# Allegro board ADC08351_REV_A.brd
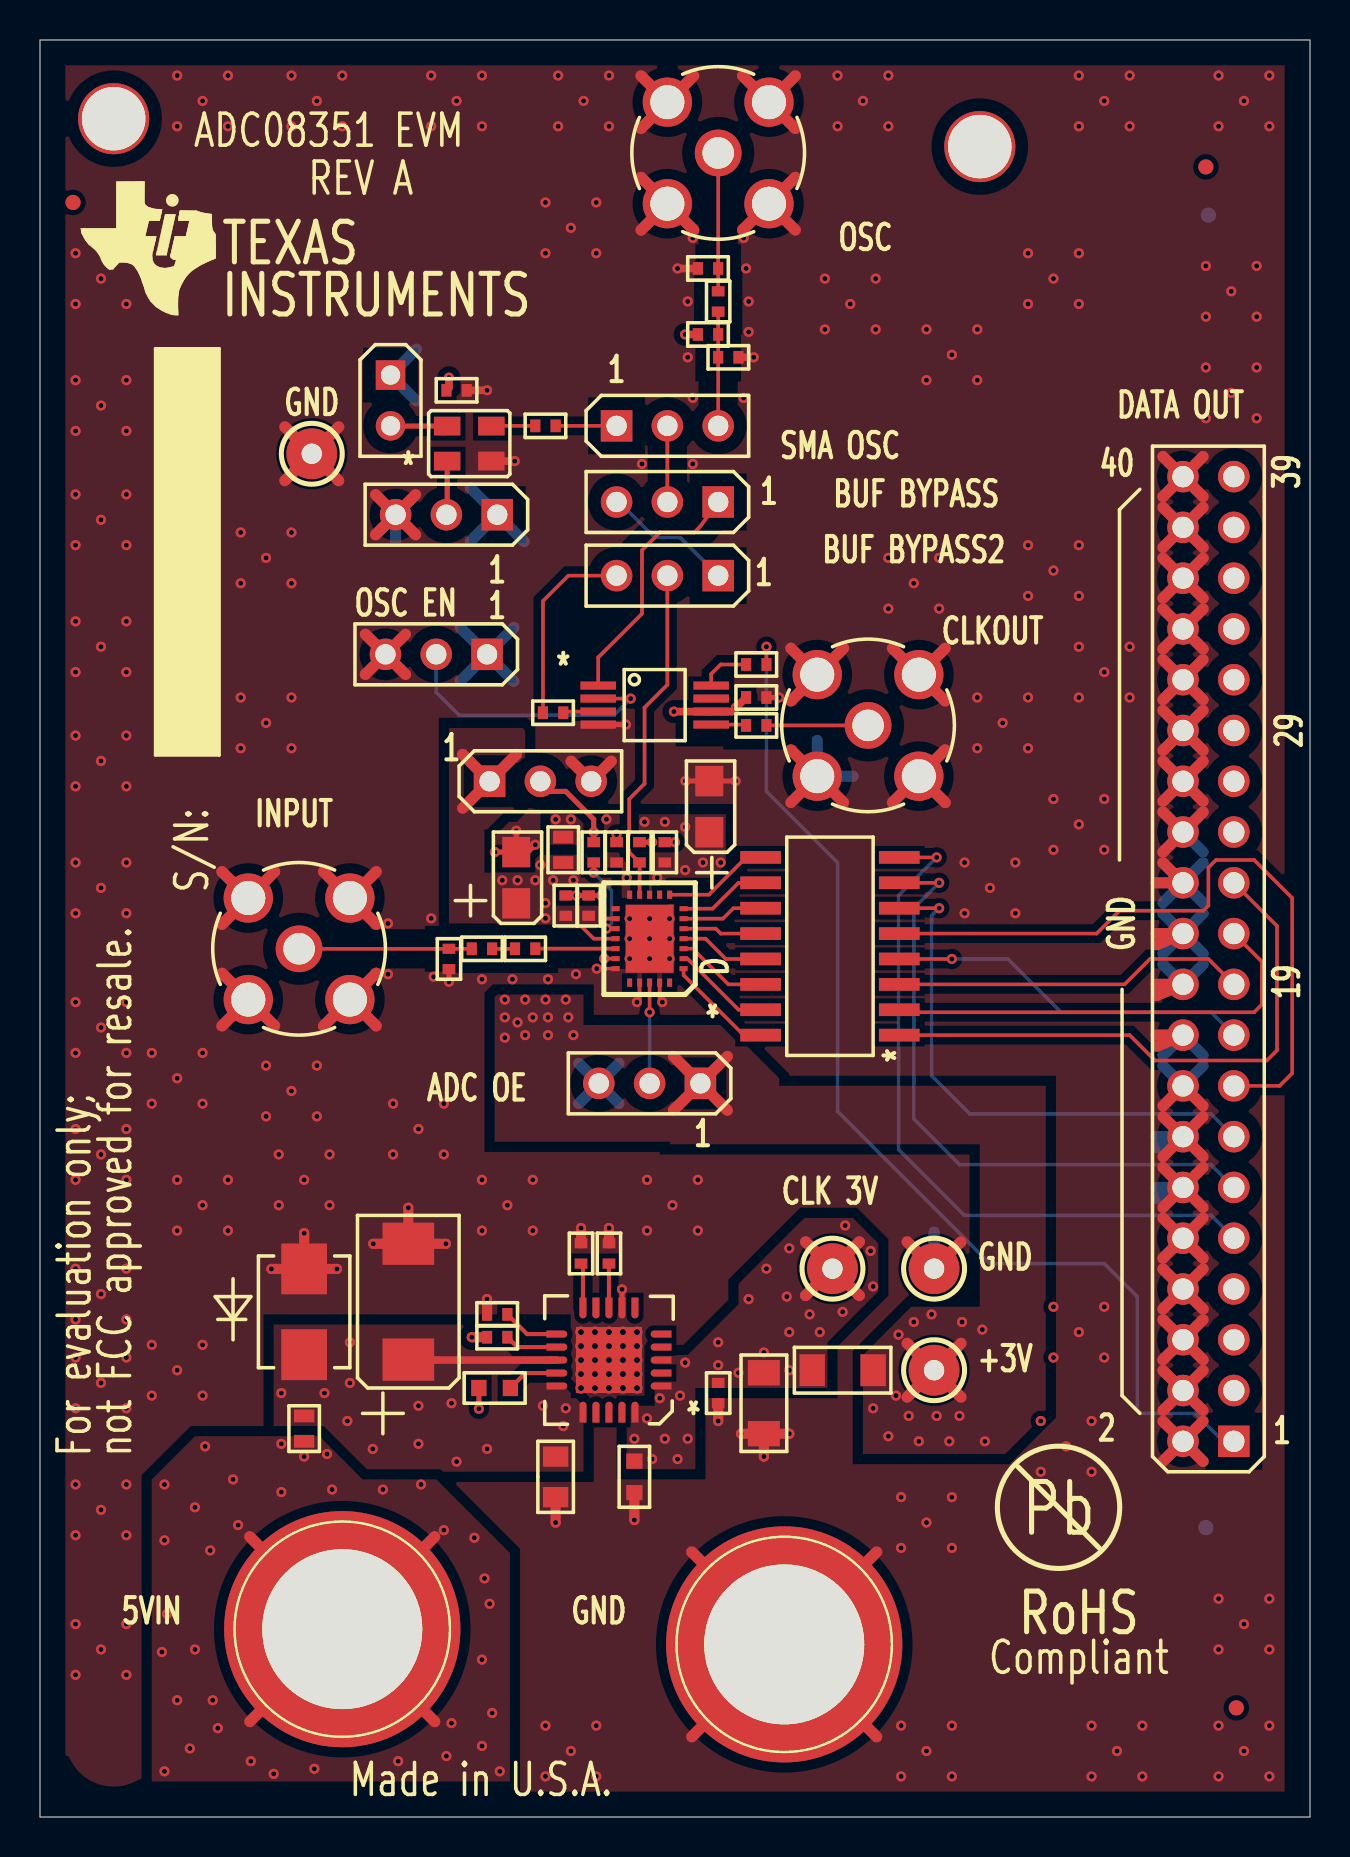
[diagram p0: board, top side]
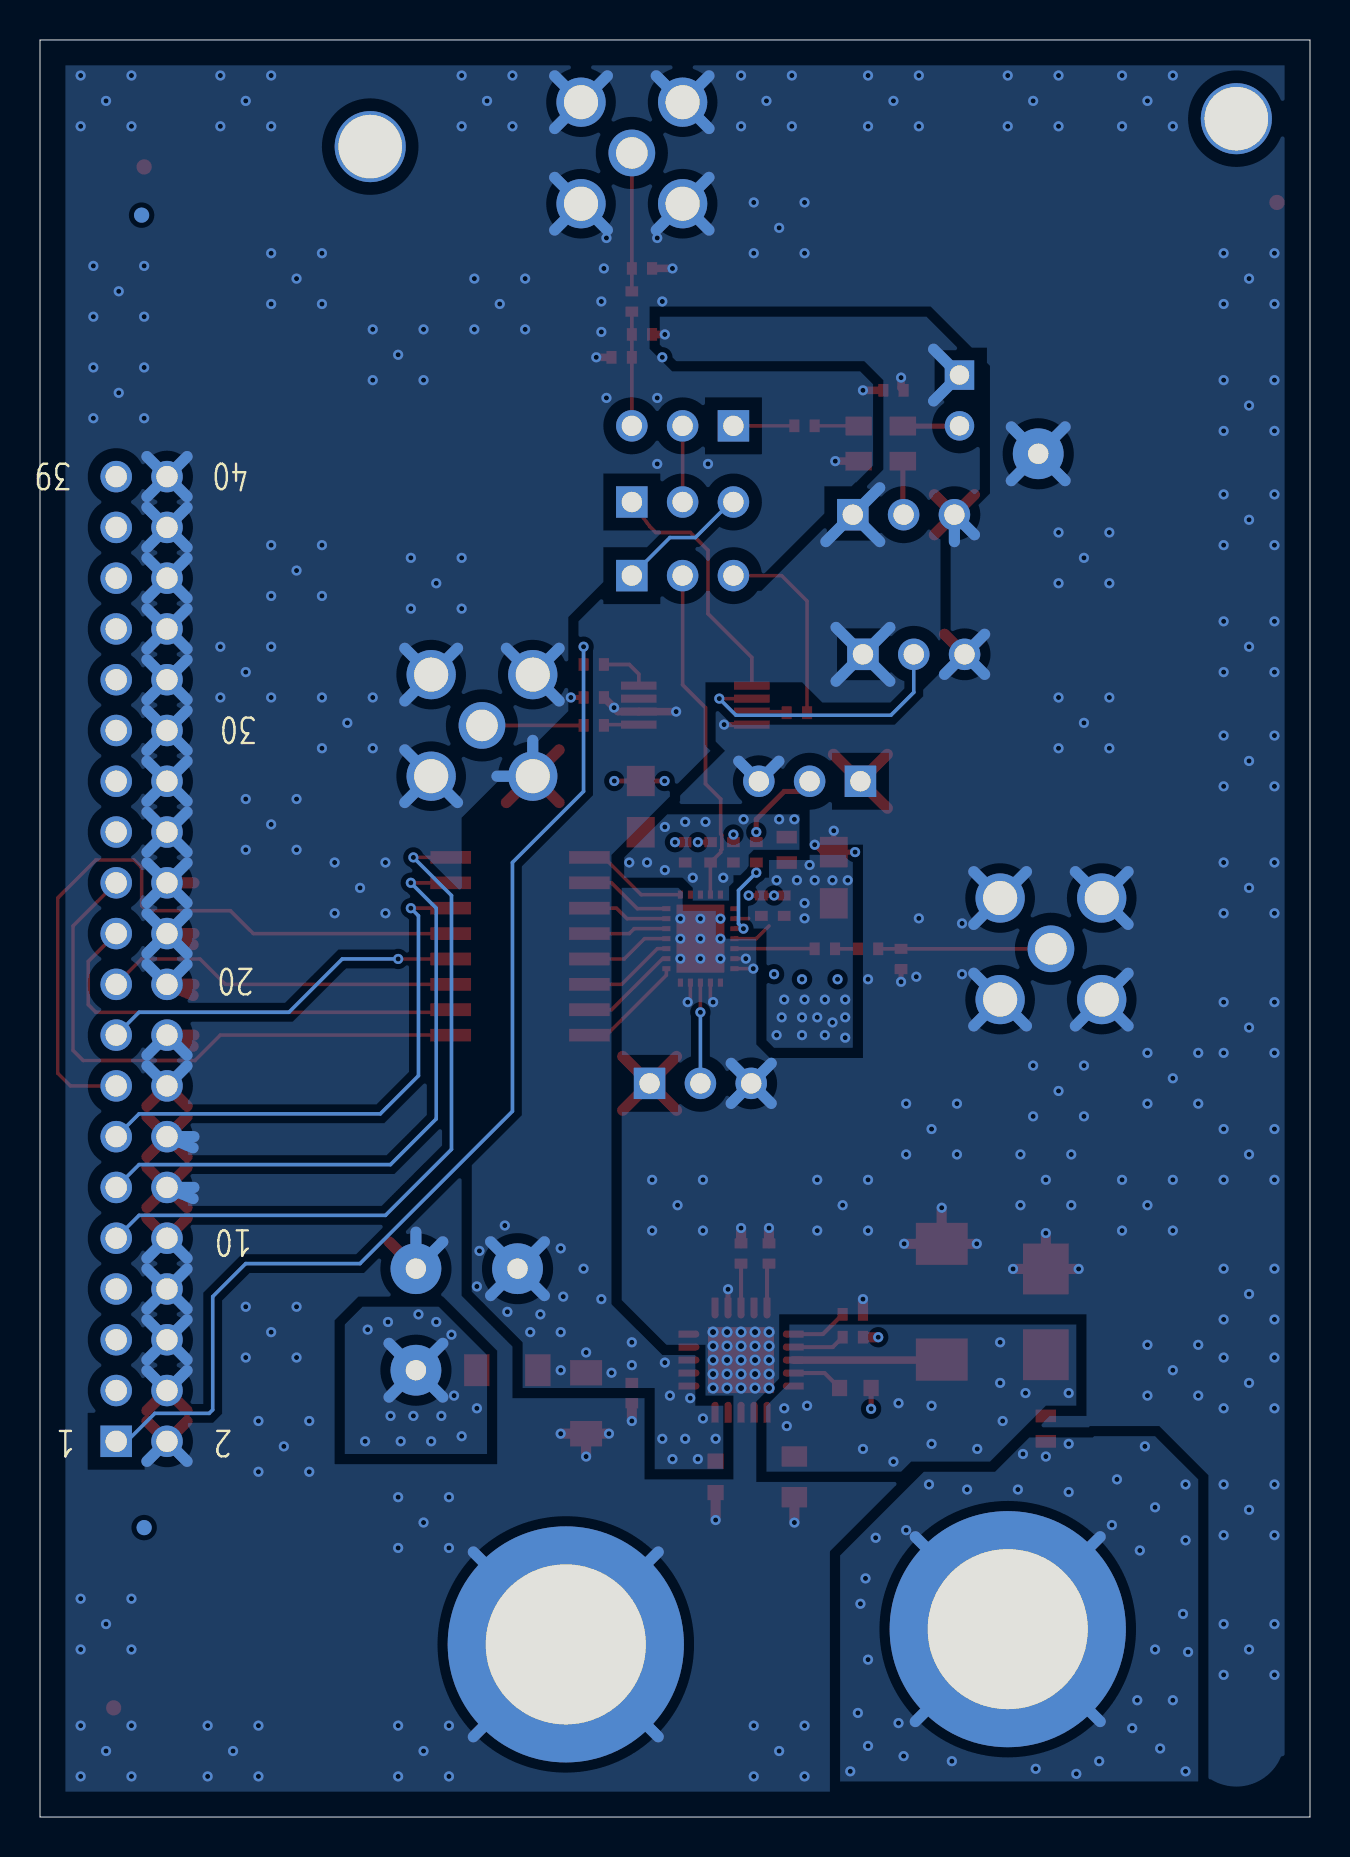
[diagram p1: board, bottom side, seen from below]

Outline 63.5 x 88.9 mm; copper layers: TOP, GND1, GND2, BOTTOM. Coordinates in mm from the lower left corner of the outline.
Outline path: 0,88.9 0,0 63.5,0 63.5,88.9 0,88.9

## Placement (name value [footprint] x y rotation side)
C1  10uF  [TANT_A]  23.81 46.99 90 top
C2  .1uF  [0402]  27.43 45.59 90 top
C3  .1uF  [0402]  26.29 45.59 90 top
C4  10uF  [TANT_A]  33.46 50.55 90 top
C5  .1uF  [0402]  28.83 48.26 90 top
C6  .1uF  [0402]  31.24 48.26 90 top
C7  2.2uF  [0402]  22.1 43.43 0 top
C8  .01uF  [0402]  20.83 71.37 0 top
C9  .1uF  [0402]  33.91 75.82 270 top
C10  100uF  [TANT_D]  18.41 25.78 90 top
C11  10uF  [0805]  25.78 17.02 270 top
C12  .1uF  [0402]  33.91 21.21 270 top
C13  1.0uF  [0603]  29.72 17.02 270 top
C14  47uF  [1206]  36.2 20.7 270 top
C20  1.0uF  [0603]  22.73 21.46 180 top
C21  .1uF  [0402]  35.81 56.01 0 top
D1  S1AB-13-F  [DIODE_S1AB_SMB]  13.21 25.27 90 top
FB1  600 OHM @ 100MHz  [IND_0603]  26.16 48.39 90 top
FB2  330 OHM @ 100MHz  [IND_0603]  13.21 19.43 90 top
FB3  120 OHM @ 100MHz  [1206]  40.13 22.35 0 top
J1  HDR, THVT, 40POS, .100  [HDR_THVT_2X20_100_M]  59.69 18.8 180 top
J2  SMA, THVT,  50OHMS  [SMA_THVT_312X312]  12.95 43.43 90 top
J3  SMA, THVT,  50OHMS  [SMA_THVT_312X312]  33.91 83.25 0 top
J4  RED  [JACK_THVT_BANANA_315DRILL]  15.11 9.4 90 top
J5  BLK  [JACK_THVT_BANANA_315DRILL]  37.21 8.64 90 top
J6  SMA, THVT,  50OHMS  [SMA_THVT_312X312]  41.4 54.61 0 top
JP1  HEADER, 3POS, .100  [HDR_THVT_1X3_100_M]  33.02 36.7 270 top
JP2  HEADER, 3POS, .100  [HDR_THVT_1X3_100_M]  28.83 69.6 90 top
JP3  HEADER, 3POS, .100  [HDR_THVT_1X3_100_M]  33.91 65.79 270 top
JP4  HEADER, 3POS, .100  [HDR_THVT_1X3_100_M]  22.35 58.17 270 top
JP5  HEADER, 3POS, .100  [HDR_THVT_1X3_100_M]  33.91 62.1 270 top
JP6  HEADER, 3POS, .100  [HDR_THVT_1X3_100_M]  22.48 51.82 90 top
JP8  HDR, 2POS, .100  [HDR_THVT_1X2_100_M]  17.53 72.14 0 top
JP9  HEADER, 3POS, .100  [HDR_THVT_1X3_100_M]  22.86 65.15 270 top
MT1  STANDOFF, FEMALE, 4-40 X  1/4"  [MFG125_PLATED]  3.68 84.96 0 top
MT4  STANDOFF, FEMALE, 4-40 X  1/4"  [MFG125_PLATED]  46.99 83.57 0 top
NOREF  -  []  258.7 174.12 0 top
NOREF#2  -  [unnamed#2]  58.29 82.55 0 top
NOREF#3  -  []  8.32 46.15 90 top
NOREF#4  -  []  51.94 8.78 0 top
NOREF#5  -  []  5.71 57.53 0 top
NOREF#6  -  []  0 0 90 top
NOREF#7  -  []  2.04 75.14 0 top
NOREF#8  -  []  0 88.9 0 top
NOREF#9  -  []  48.9 14.22 0 top
NOREF#10  -  [unnamed#2]  59.82 5.46 0 top
NOREF#11  -  []  2.44 17.93 90 top
NOREF#12  -  [unnamed#2]  1.65 80.77 0 top
NOREF#13  -  []  15.37 1.14 0 top
NOREF#14  -  []  185.29 62.97 0 top
NOREF#15  -  []  84.84 78.11 180 bottom
NOREF#16  -  [unnamed#2]  58.42 80.14 180 bottom
NOREF#17  -  [unnamed#2]  58.29 14.48 180 bottom
R2  47  [0402]  24.26 43.43 0 top
R3  51  [0402]  20.45 42.93 270 top
R4  330  [0402]  29.97 48.26 90 top
R5  10k  [0402]  27.69 48.26 90 top
R8  100  [0402]  33.4 74.17 0 top
R9  49.9  [0402]  33.4 77.47 0 top
R10  100  [0402]  34.42 73.02 0 top
R11  0  [0402]  22.86 24 0 top
R12  0  [0402]  22.86 25.15 0 top
R13  0  [0402]  27.05 28.19 270 top
R14  0  [0402]  28.45 28.19 270 top
R15  22.1  [0402]  25.65 55.24 0 top
R16  22.1  [0402]  35.81 54.61 0 top
R18  22.1  [0402]  35.81 57.66 0 top
R19  22.1  [0402]  25.27 69.6 180 top
RN1  22 OHM  [RNET_16_225X445_50]  39.5 41.66 90 top
TP1  BLK  [TP_THVT_100_RND_GND]  13.59 68.2 90 top
TP2  BLU  [TP_THVT_100_RND]  44.7 22.35 0 top
TP3  BLK  [TP_THVT_100_RND_GND]  44.7 27.43 0 top
TP4  BLU  [TP_THVT_100_RND]  39.62 27.43 0 top
U1  ADC08351  [WQFN_24_157X197_0P50MM]  30.48 43.94 180 top
U2  TPS7A4700  [QFN20_RGW_P65PITCH]  28.45 22.86 180 top
U3  CDCV304PW  [TSSOP_8_177X122_26]  30.73 55.63 0 top
Y1  40MHz  [XTAL_4_SM_102X130]  21.46 68.71 0 top

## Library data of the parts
C1 C4 = CAP_TANT_A_0
C2 C3 C5 C6 C9 C21 = CAP_0402_0.1uF
C7 = CAP_0402_2.2uF
C8 = CAP_0402_0.01uF
C10 = CAP_TANT_D_0
C11 = CAP NP_1: tolerance: 10%
C12 = CAP0603: tolerance: 10%
C13 C20 = CAP NP_0: tolerance: 10%
C14 = CAP NP_0: tolerance: 20%
D1 = DIODE_S1BB
FB1 FB2 = FERRITE_BEAD_0603_600_H
FB3 = FERRITE_BEAD_1206_120_H
J1 = HEADER_2x20_100
J2 J3 J6 = TMP_102603
J4 = BANANA_JACK_RED_RoHS
J5 = BANANA_JACK_BLK_RoHS
JP1-JP6 JP9 = JUMPER_1X3_100
JP8 = JUMPER_1X2_100
MT1 MT4 = MOUNTING_HOLE_1_3/16"
R2 = Res_0402_47
R3 = Res_0402_51_.5%: tolerance: .1%
R4 = Res_0402_330
R5 = Res_0402_10k
R8 R10 = Res_0402_100
R9 = Res_0402_49.9_H
R11-R14 = R: tolerance: 5%
R15 R16 R18 R19 = Res_0402_22.1_H
RN1 = RESNW_IS_8
TP1 TP3 = TESTPOINT_BLK
TP2 TP4 = TESTPOINT_BLUE
U1 = ADC08351
U2 = TPS7A4700
U3 = CDCV304PW
Y1 = OSC_4_SM_KYOCERA_40MHz

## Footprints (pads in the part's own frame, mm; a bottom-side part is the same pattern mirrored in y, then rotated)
0402
  rect 0.508x0.635 smd: 1(-0.508,0) 2(0.508,0)
0603
  rect 0.762x0.813 smd: 1(-0.787,0) 2(0.787,0)
0805
  rect 1.016x1.27 smd: 1(-1.016,0) 2(1.016,0)
1206
  rect 1.27x1.6 smd: 1(-1.524,0) 2(1.524,0)
DIODE_S1AB_SMB
  rect 2.54x2.286 smd: 1(2.146,0) 2(-2.146,0)
HDR_THVT_1X2_100_M
  rect 1.473x1.473 hole 0.965: 1(0,0)
  round 1.473 hole 0.965: 2(0,-2.54)
HDR_THVT_1X3_100_M
  rect 1.575x1.575 hole 1.016: 1(0,0)
  round 1.575 hole 1.016: 2(0,-2.54) 3(0,-5.08)
HDR_THVT_2X20_100_M
  rect 1.575x1.575 hole 1.067: 1(0,0)
  round 1.575 hole 1.067: 2(2.54,0) 3(0,-2.54) 4(2.54,-2.54) 5(0,-5.08) 6(2.54,-5.08) 7(0,-7.62) 8(2.54,-7.62) 9(0,-10.16) 10(2.54,-10.16) 11(0,-12.7) 12(2.54,-12.7) 13(0,-15.24) 14(2.54,-15.24) 15(0,-17.78) 16(2.54,-17.78) 17(0,-20.32) 18(2.54,-20.32) 19(0,-22.86) 20(2.54,-22.86) 21(0,-25.4) 22(2.54,-25.4) 23(0,-27.94) 24(2.54,-27.94) 25(0,-30.48) 26(2.54,-30.48) 27(0,-33.02) 28(2.54,-33.02) 29(0,-35.56) 30(2.54,-35.56) 31(0,-38.1) 32(2.54,-38.1) 33(0,-40.64) 34(2.54,-40.64) 35(0,-43.18) 36(2.54,-43.18) 37(0,-45.72) 38(2.54,-45.72) 39(0,-48.26) 40(2.54,-48.26)
IND_0603
  rect 0.635x1.016 smd: 1(-0.635,0) 2(0.635,0)
JACK_THVT_BANANA_315DRILL
  round 11.811 hole 8.001: 1(0,0)
MFG125_PLATED
  round 3.556 hole 3.175: 1(0,0)
QFN20_RGW_P65PITCH
  custom 0.09x0.09 smd: 1(-2.607,1.3) 2(-2.607,0.65) 3(-2.607,0) 4(-2.607,-0.65) 5(-2.607,-1.3) 6(-1.3,-2.607) 7(-0.65,-2.607) 8(0,-2.607) 9(0.65,-2.607) 10(1.3,-2.607) 11(2.607,-1.3) 12(2.607,-0.65) 13(2.607,0) 14(2.607,0.65) 15(2.607,1.3) 16(1.3,2.607) 17(0.65,2.607) 18(0,2.607) 19(-0.65,2.607) 20(-1.3,2.607)
  rect 3.302x3.302 smd: 21(0,0)
RNET_16_225X445_50
  rect 0.635x2.032 smd: 1(-2.54,-3.467) 2(-1.27,-3.467) 3(0,-3.467) 4(1.27,-3.467) 5(2.54,-3.467) 6(3.81,-3.467) 7(5.08,-3.467) 8(6.35,-3.467) 9(6.35,3.467) 10(5.08,3.467) 11(3.81,3.467) 12(2.54,3.467) 13(1.27,3.467) 14(0,3.467) 15(-1.27,3.467) 16(-2.54,3.467)
SMA_THVT_312X312
  round 2.337 hole 1.575: 1(0,0)
  round 2.464 hole 1.702: 2(-2.54,2.54) 3(2.54,2.54) 4(2.54,-2.54) 5(-2.54,-2.54)
TANT_A
  rect 1.524x1.397 smd: 1(-1.283,0) 2(1.283,0)
TANT_D
  rect 2.108x2.591 smd: 1(-2.896,0) 2(2.896,0)
TP_THVT_100_RND
  round 2.54 hole 1.016: 1(0,0)
TP_THVT_100_RND_GND
  round 2.54 hole 1.016: 1(0,0)
TSSOP_8_177X122_26
  rect 1.778x0.406 smd: 1(-2.825,0.975) 2(-2.825,0.325) 3(-2.825,-0.325) 4(-2.825,-0.975) 5(2.825,-0.975) 6(2.825,-0.325) 7(2.825,0.325) 8(2.825,0.975)
unnamed#2
  round 0.762 smd: (0,0)
WQFN_24_157X197_0P50MM
  rect 0.406x0.254 smd: 1(-1.7,1.5) 2(-1.7,1) 3(-1.7,0.5) 4(-1.7,0) 5(-1.7,-0.5) 6(-1.7,-1) 7(-1.7,-1.5) 13(1.7,-1.5) 14(1.7,-1) 15(1.7,-0.5) 16(1.7,0) 17(1.7,0.5) 18(1.7,1) 19(1.7,1.5)
  rect 0.254x0.406 smd: 8(-1,-2.2) 9(-0.5,-2.2) 10(0,-2.2) 11(0.5,-2.2) 12(1,-2.2) 20(1,2.2) 21(0.5,2.2) 22(0,2.2) 23(-0.5,2.2) 24(-1,2.2)
  rect 2.4x3.4 smd: 25(0,0)
XTAL_4_SM_102X130
  rect 1.321x0.94 smd: 1(-1.105,-0.876) 2(1.105,-0.876) 3(1.105,0.876) 4(-1.105,0.876)

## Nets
5V: FB2.1 J4.1
+3V: C1.1 C2.1 C3.1 FB1.1 FB3.2 JP1.1(PIN1) JP6.1(PIN1) TP2.1(TP) U1.14(VREF) U1.16(VA)
+5V: C10.1 C11.1 D1.2(CATHODE) FB2.2 U2.13(EN) U2.15(IN2) U2.16(IN1)
GND: C1.2 C2.2 C3.2 C4.2 C5.2 C6.2 C8.2 C10.2 C11.2 C12.2 C13.2 C14.2 C20.2 C21.2 D1.1(ANODE) J1.2 J1.4 J1.6 J1.8 J1.10 J1.12 J1.14 J1.16 J1.18 J1.20 J1.22 J1.24 J1.26 J1.28 J1.30 J1.32 J1.34 J1.36 J1.38 J1.40 J2.2(GND#2) J2.3(GND#3) J2.4(GND#4) J2.5(GND#5) J3.2(GND#2) J3.3(GND#3) J3.4(GND#4) J3.5(GND#5) J5.1 J6.2(GND#2) J6.3(GND#3) J6.4(GND#4) J6.5(GND#5) JP1.3(PIN3) JP4.3(PIN3) JP6.3(PIN3) JP9.3(PIN3) R3.2 R4.2 R9.1 R10.2 R11.1 R12.1 R13.1 R14.1 TP1.1(TP) TP3.1(TP) U1.18(AGND1) U1.19(AGND2) U1.21(DGND1) U1.23(DGND2) U1.25(PWRPAD) U2.7(GND) U2.21(PWRPAD) U3.4(GND) Y1.2(GND)
VIN: R2.2 U1.17(VIN)
ADC_CLK: JP2.2(PIN2) JP3.2(PIN2)
CLK: JP5.2(PIN2) R4.1 U1.11(CLK)
CLK_3V: C8.1 C12.1 C13.1 C14.1 C21.1 FB3.1 JP4.1(PIN1) JP8.1 JP9.1(PIN1) R8.1 TP4.1(TP) U2.1(OUT1) U2.3(SENSE) U2.20(OUT2) U3.6(VDD3.3V)
CLK_OUT: J6.1(CENTER) R16.2
CLKIN: JP3.1(PIN1) U3.1(CLKIN)
CLKOUT: R16.1 U3.5(X1Y1)
D0: RN1.16 U1.1(D0)
D1: RN1.15 U1.2(D1)
D2: RN1.14 U1.3(D2)
D3: RN1.13 U1.4(D3)
D4: RN1.12 U1.5(D4)
D5: RN1.11 U1.6(D5)
D6: RN1.10 U1.7(D6)
D7: RN1.9 U1.8(D7)
IN: C7.2 R2.1
INPUT: C7.1 J2.1(CENTER) R3.1
OE: JP4.2(PIN2) U3.2(OE)
OEN: JP1.2(PIN2) U1.22(\\O\E\)
OSC: C9.1 J3.1(CENTER) R9.2
OSC1: C9.2 JP2.3(PIN3) R8.2 R10.1
N19763021: C4.1 C5.1 C6.1 FB1.2 U1.10(VD#10) U1.12(VD#12)
N19764908: R5.1 U1.15(PD)
N19769118: R19.2 Y1.3(OUT)
N19769226: JP2.1(PIN1) R19.1
N19785120: C20.1 U2.14(NR)
N19785142: R14.2 U2.8(1P6V)
N19785144: R12.2 U2.11(0P2V)
N19785146: R11.2 U2.12(0P1V)
N19785156: R13.2 U2.10(0P4V)
N19799665: R15.2 U3.3(X1Y0)
N19799687: R18.1 U3.8(X1Y3)
N19799717: J1.1 R18.2
N19818955: J1.23 RN1.1
N19818957: J1.21 RN1.2
N19818959: J1.19 RN1.3
N19818961: J1.17 RN1.4
N19819026: J1.9 RN1.8
N19819028: J1.11 RN1.7
N19819030: J1.13 RN1.6
N19819032: J1.15 RN1.5
N19819185: JP3.3(PIN3) JP5.1(PIN1)
N19819218: JP5.3(PIN3) R15.1
N19819979: JP6.2(PIN2) R5.2
N19821064: JP9.2(PIN2) Y1.1(INH)
N19821339: JP8.2 Y1.4(VDD)

Pads without a net: J1 3 5 7 25 27 29 31 33 35 37 39; MT1 1; MT4 1; U1 9 13 20 24; U2 2 4 5 6 9 17 18 19; U3 7

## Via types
v1: diameter 0.508, hole 0.254, TOP to BOTTOM, 447 vias
v2: diameter 0.559, hole 0.305, TOP to BOTTOM, 25 vias

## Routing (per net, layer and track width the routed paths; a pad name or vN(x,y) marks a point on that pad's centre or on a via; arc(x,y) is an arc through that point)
5V: length 52.3
  TOP w0.559: J4.1 19.74,4.78 ; J4.1 19.74,14.02 ; J4.1 10.49,14.02 ; J4.1 10.49,4.78
  BOTTOM w0.559: J4.1 19.74,14.02 ; J4.1 10.49,4.78 ; J4.1 10.49,14.02 ; J4.1 19.74,4.78
  vias: v1(6.1,8.25) v1(6.22,16.64) v1(6.22,13.84) v1(6.22,2.29) v1(6.35,10.16) v1(6.86,5.84) v1(7.49,3.43) v1(7.75,15.49) v1(7.75,8.38) v1(8.25,18.54) v1(8.51,13.33) v1(8.64,5.84) v1(8.89,4.45) v1(9.65,16.89) v1(9.91,14.6) v1(10.54,2.79) v1(11.68,2.16) v1(12.06,18.67) v1(12.06,16.26) v1(13.21,18.03) v1(13.72,2.41) v1(14.35,18.16) v1(14.61,16.38) v1(17.14,16.38) v1(17.91,2.79) v1(19.05,16.64) v1(20.19,14.35) v1(20.32,3.05) v1(20.57,4.7) v1(21.72,13.97) v1(22.1,7.87) v1(22.1,3.56) v1(22.23,11.94) v1(22.48,10.67) v1(22.61,5.21) v1(22.99,2.29)
+3V: length 31.3
  TOP w0.178: 27.05,44.58 27.69,43.94 U1.16 ; U1.14 28.08,44.94 28.07,44.96
  TOP w0.559: JP1.1 34.37,38.05 ; JP1.1 31.67,38.05 ; JP1.1 31.67,35.36 ; JP1.1 34.37,35.36 ; TP2.1 46.05,23.7 ; TP2.1 43.36,21.01 ; TP2.1 46.05,21.01 ; TP2.1 43.36,23.7 ; 21.13,53.16 JP6.1 ; JP6.1 23.83,53.16 ; JP6.1 21.13,50.47
  BOTTOM w0.559: 43.36,23.7 TP2.1 ; TP2.1 43.36,21.01 ; TP2.1 46.05,23.7 ; TP2.1 46.05,21.01
  vias: v1(23.11,46.86) v1(23.24,40.89) v1(23.24,40) v1(23.24,38.99) v1(23.88,46.86) v1(23.88,39.75) v1(24.26,40.89) v1(24.26,39.12) v1(24.64,40) v1(24.77,46.86) v1(25.02,47.62) v1(25.27,45.72) v1(25.27,44.96) v1(25.27,40.89) v1(25.4,40) v1(25.4,39.12) v1(25.65,46.86) v1(26.29,40.89) v1(26.42,40) v1(26.67,46.86) v1(26.67,39.12) v1(41.66,20.45) v1(42.42,19.05) v1(42.8,21.08) v1(42.93,24.13) v1(43.43,20.07) v1(43.69,24.77) v1(43.94,18.8) v1(44.58,25.15) v1(44.83,20.07) v1(45.47,18.8) v1(45.97,20.07) v1(46.1,24.77) v1(47.12,24.38) v1(47.24,18.8)
+5V: length 6.2
  TOP w0.381: U2.13 19.68,22.86
  vias: v1(12.06,21.21) v1(14.22,21.21) v1(15.37,19.81) v1(15.49,23.75) v1(15.49,21.72) v1(16.64,18.41) v1(18.92,20.57) v1(18.92,18.67) v1(20.57,20.7) v1(20.83,17.78) v1(22.35,18.41) v1(25.15,20.57) v1(26.16,19.56) v1(26.29,20.45)
GND: length 956.2
  TOP w0.178: U1.23 30.98,40.9 v1(31.11,40.77) ; U1.18 v1(28.21,42.94) ; v1(29.84,40.77) 29.98,40.9 U1.21 ; U1.19 v1(27.84,42.44)
  TOP w0.254: U2.7 v1(29.1,26.4) ; v1(34.79,51.83) C4.2 v1(32.27,51.83) ; C20.2 v1(21.95,20.42) ; C6.2 v1(31.75,48.77) ; R4.2 v1(30.61,48.77) ; v1(28.07,46.1) C2.2 v1(26.8,46.1) C3.2 ; v1(24.77,48.64) 24.4,48.27 C1.2 ; C1.2 v1(22.75,48.27) ; C1.2 v1(23.81,49.34) ; C5.2 v1(28.83,49.15) ; U3.4 v1(29.3,54.65) ; C21.2 v1(36.96,56.01) ; R3.2 v1(20.45,41.78)
  TOP w0.381: R9.1 v1(31.88,77.47) ; C8.2 v1(22.35,71.37) ; R10.2 v1(35.69,73.02) ; Y1.2 v1(23.74,67.83)
  TOP w0.508: D1.1 v1(13.21,29.21) ; D1.1 v1(14.85,27.42) ; D1.1 v1(11.57,27.42) ; C10.2 v1(16.66,28.68) ; C10.2 v1(18.41,30.48) ; C10.2 v1(20.29,28.68) ; R14.1 v1(28.45,29.46) ; R13.1 v1(27.05,29.46) ; C11.2 v1(25.78,14.73) ; C14.2 v1(35.05,19.18) ; C14.2 v1(37.46,19.18) ; C14.2 v1(36.2,18.03) ; C12.2 v1(33.91,19.81) ; R12.1 v1(22.35,25.91) ; C13.2 v1(29.72,14.86) ; R11.1 v1(21.59,24)
  TOP w0.559: 56.15,68.06 J1.40 ; J1.40 58.15,68.06 ; J1.40 58.15,66.05 ; J1.40 56.15,66.05 ; J1.10 58.15,27.95 ; J1.10 58.15,29.96 ; J1.10 56.15,27.95 ; J1.10 56.15,29.96 ; J2.4 16.81,44.66 ; J2.4 14.18,47.29 ; J2.4 16.81,47.29 ; 28.56,52.82 JP6.3 26.56,52.82 ; J3.2 32.69,87.11 ; J3.2 30.05,84.47 ; J3.2 30.05,87.11 ; 56.15,32.5 57.15,31.5 ; 57.15,31.5 58.15,30.49 ; 57.15,31.5 56.15,30.49 ; 57.15,31.5 58.15,32.5 ; 37.54,50.75 J6.5 ; J6.5 40.18,50.75 ; J6.5 37.54,53.39 ; 37.54,58.47 J6.2 ; J6.2 40.18,58.47 ; J6.2 37.54,55.83 ; JP9.3 18.78,66.15 ; JP9.3 16.78,64.15 ; JP9.3 18.78,64.15 ; JP9.3 16.78,66.15 ; J2.3 11.73,47.29 ; J2.3 9.1,44.66 ; J2.3 9.1,47.29 ; J3.5 32.69,79.39 ; J3.5 30.05,82.03 ; J3.5 30.05,79.39 ; J1.34 58.15,60.44 ; J1.34 56.15,58.43 ; J1.34 56.15,60.44 ; J1.34 58.15,58.43 ; 56.15,50.81 J1.28 ; J1.28 58.15,50.81 ; J1.28 56.15,52.82 ; J1.28 58.15,52.82 ; 56.15,57.9 J1.32 ; J1.32 56.15,55.89 ; J1.32 58.15,57.9 ; J1.32 58.15,55.89 ; 14.18,39.58 J2.5 ; J2.5 16.81,39.58 ; J2.5 16.81,42.21 ; J3.3 37.77,84.47 ; J3.3 37.77,87.11 ; J3.3 35.13,87.11 ; J1.6 58.15,22.87 ; J1.6 56.15,22.87 ; J1.6 56.15,24.88 ; J1.6 58.15,24.88 ; 56.15,53.35 J1.30 ; J1.30 58.15,53.35 ; J1.30 56.15,55.36 ; J1.30 58.15,55.36 ; 16.27,57.16 JP4.3 ; JP4.3 16.27,59.17 ; JP4.3 18.28,59.17 ; JP4.3 18.28,57.16 ; 35.13,79.39 J3.4 ; J3.4 37.77,79.39 ; J3.4 37.77,82.03 ; J1.38 58.15,63.51 ; J1.38 56.15,65.52 ; J1.38 56.15,63.51 ; J1.38 58.15,65.52 ; 58.15,35.57 J1.16 56.15,35.57 ; 56.15,47.74 J1.24 55.8,46.74 ; J6.4 45.26,50.75 ; J6.4 45.26,53.39 ; J6.4 42.62,50.75 ; 56.15,20.33 J1.4 ; J1.4 58.15,20.33 ; J1.4 58.15,22.34 ; J1.4 56.15,22.34 ; 56.15,35.04 J1.14 ; J1.14 56.15,33.03 ; J1.14 58.15,35.04 ; J1.14 58.15,33.03 ; 46.05,28.78 TP3.1 43.36,28.78 ; J1.8 58.15,27.42 ; J1.8 58.15,25.41 ; J1.8 56.15,27.42 ; J1.8 56.15,25.41 ; 32.59,13.26 J5.1 ; J5.1 41.83,4.01 ; J5.1 41.83,13.26 ; J5.1 32.59,4.01 ; 56.15,17.79 J1.2 ; J1.2 56.15,19.8 ; J1.2 58.15,19.8 ; J1.2 58.15,17.79 ; J6.3 45.26,58.47 ; J6.3 42.62,58.47 ; J6.3 45.26,55.83 ; 56.15,60.97 J1.36 ; J1.36 58.15,60.97 ; J1.36 56.15,62.98 ; J1.36 58.15,62.98 ; 55.85,43.64 J1.22 55.8,44.2 ; 55.85,41.1 J1.20 55.8,41.66 ; J1.26 58.15,50.28 ; J1.26 56.15,50.28 ; J1.26 56.15,48.27 ; 55.85,38.56 J1.18 55.8,39.12 ; TP1.1 14.93,69.54 ; TP1.1 14.93,66.85 ; TP1.1 12.24,66.85 ; TP1.1 12.24,69.54 ; 9.1,39.58 J2.2 ; J2.2 9.1,42.21 ; J2.2 11.73,39.58
  GND1 w0.559: 56.15,24.88 J1.6 ; J1.6 58.15,24.88 ; J1.6 58.15,22.87 ; J1.6 56.15,22.87 ; J1.30 58.15,53.35 ; J1.30 58.15,55.36 ; J1.30 56.15,55.36 ; J1.30 56.15,53.35 ; 30.05,87.11 J3.2 ; J3.2 32.69,87.11 ; J3.2 30.05,84.47 ; J1.34 58.15,60.44 ; J1.34 58.15,58.43 ; J1.34 56.15,58.43 ; J1.34 56.15,60.44 ; 56.15,47.74 J1.24 ; J1.24 58.15,45.73 ; J1.24 58.15,47.74 ; J1.24 56.15,45.73 ; JP9.3 18.78,64.15 ; JP9.3 18.78,66.15 ; JP9.3 16.78,64.15 ; JP9.3 16.78,66.15 ; J2.5 16.81,42.21 ; J2.5 16.81,39.58 ; J2.5 14.18,39.58 ; J1.16 58.15,35.57 ; J1.16 56.15,37.58 ; J1.16 56.15,35.57 ; J1.16 58.15,37.58 ; J6.3 45.26,55.83 ; J6.3 45.26,58.47 ; J6.3 42.62,58.47 ; 57.15,31.5 58.15,30.49 ; 57.15,31.5 56.15,30.49 ; 57.15,31.5 58.15,32.5 ; 57.15,31.5 56.15,32.5 ; TP3.1 46.05,28.78 ; TP3.1 46.05,26.09 ; TP3.1 43.36,26.09 ; TP3.1 43.36,28.78 ; 56.15,25.41 J1.8 ; J1.8 58.15,27.42 ; J1.8 56.15,27.42 ; J1.8 58.15,25.41 ; J1.26 58.15,48.27 ; J1.26 58.15,50.28 ; J1.26 56.15,48.27 ; J1.26 56.15,50.28 ; J1.40 58.15,68.06 ; J1.40 56.15,68.06 ; J1.40 56.15,66.05 ; J1.40 58.15,66.05 ; 56.15,19.8 J1.2 ; J1.2 58.15,19.8 ; J1.2 56.15,17.79 ; J1.2 58.15,17.79 ; 37.54,50.75 J6.5 ; J6.5 37.54,53.39 ; J6.5 40.18,50.75 ; 56.15,27.95 J1.10 ; J1.10 56.15,29.96 ; J1.10 58.15,29.96 ; J1.10 58.15,27.95 ; J3.5 32.69,79.39 ; J3.5 30.05,79.39 ; J3.5 30.05,82.03 ; 56.15,40.65 J1.20 ; J1.20 58.15,42.66 ; J1.20 58.15,40.65 ; J1.20 56.15,42.66 ; JP4.3 18.28,57.16 ; JP4.3 16.27,59.17 ; JP4.3 18.28,59.17 ; JP4.3 16.27,57.16 ; 56.15,65.52 J1.38 ; J1.38 58.15,63.51 ; J1.38 58.15,65.52 ; J1.38 56.15,63.51 ; TP1.1 14.93,69.54 ; TP1.1 14.93,66.85 ; TP1.1 12.24,69.54 ; TP1.1 12.24,66.85 ; J1.36 58.15,60.97 ; J1.36 58.15,62.98 ; J1.36 56.15,62.98 ; J1.36 56.15,60.97 ; 56.15,35.04 J1.14 ; J1.14 56.15,33.03 ; J1.14 58.15,33.03 ; J1.14 58.15,35.04 ; 37.54,58.47 J6.2 ; J6.2 40.18,58.47 ; J6.2 37.54,55.83 ; 9.1,42.21 J2.2 ; J2.2 9.1,39.58 ; J2.2 11.73,39.58 ; 14.18,47.29 J2.4 ; J2.4 16.81,44.66 ; J2.4 16.81,47.29 ; J3.3 37.77,84.47 ; J3.3 35.13,87.11 ; J3.3 37.77,87.11 ; J6.4 45.26,53.39 ; J6.4 45.26,50.75 ; J6.4 42.62,50.75 ; 56.15,45.2 J1.22 ; J1.22 58.15,45.2 ; J1.22 58.15,43.19 ; J1.22 56.15,43.19 ; 35.13,79.39 J3.4 ; J3.4 37.77,82.03 ; J3.4 37.77,79.39 ; 26.94,35.7 JP1.3 ; JP1.3 28.94,37.71 ; JP1.3 28.94,35.7 ; JP1.3 26.94,37.71 ; 32.59,4.01 J5.1 ; J5.1 41.83,4.01 ; J5.1 41.83,13.26 ; J5.1 32.59,13.26 ; J1.32 58.15,55.89 ; J1.32 56.15,57.9 ; J1.32 56.15,55.89 ; J1.32 58.15,57.9 ; J1.18 58.15,38.11 ; J1.18 56.15,40.12 ; J1.18 58.15,40.12 ; J1.18 56.15,38.11 ; JP6.3 28.56,50.81 ; JP6.3 26.56,50.81 ; JP6.3 28.56,52.82 ; JP6.3 26.56,52.82 ; 56.15,52.82 J1.28 ; J1.28 58.15,52.82 ; J1.28 56.15,50.81 ; J1.28 58.15,50.81 ; J1.4 58.15,20.33 ; J1.4 58.15,22.34 ; J1.4 56.15,22.34 ; J1.4 56.15,20.33 ; J2.3 11.73,47.29 ; J2.3 9.1,47.29 ; J2.3 9.1,44.66
  GND2 w0.559: J1.24 58.15,45.73 ; J1.24 56.15,45.73 ; J1.24 56.15,47.74 ; J1.24 58.15,47.74 ; 14.18,47.29 J2.4 ; J2.4 16.81,47.29 ; J2.4 16.81,44.66 ; TP3.1 46.05,28.78 ; TP3.1 43.36,26.09 ; TP3.1 46.05,26.09 ; TP3.1 43.36,28.78 ; JP4.3 18.28,59.17 ; JP4.3 18.28,57.16 ; JP4.3 16.27,57.16 ; JP4.3 16.27,59.17 ; J1.34 58.15,58.43 ; J1.34 56.15,60.44 ; J1.34 58.15,60.44 ; J1.34 56.15,58.43 ; J6.5 40.18,50.75 ; J6.5 37.54,50.75 ; J6.5 37.54,53.39 ; J1.20 58.15,42.66 ; J1.20 58.15,40.65 ; J1.20 56.15,40.65 ; J1.20 56.15,42.66 ; 57.15,31.5 58.15,30.49 ; 57.15,31.5 58.15,32.5 ; 57.15,31.5 56.15,30.49 ; 57.15,31.5 56.15,32.5 ; 26.56,52.82 JP6.3 ; JP6.3 28.56,52.82 ; JP6.3 26.56,50.81 ; JP6.3 28.56,50.81 ; J3.3 37.77,84.47 ; J3.3 35.13,87.11 ; J3.3 37.77,87.11 ; 56.15,60.97 J1.36 ; J1.36 58.15,60.97 ; J1.36 58.15,62.98 ; J1.36 56.15,62.98 ; J5.1 41.83,4.01 ; J5.1 32.59,13.26 ; J5.1 32.59,4.01 ; J5.1 41.83,13.26 ; J1.18 58.15,40.12 ; J1.18 56.15,38.11 ; J1.18 58.15,38.11 ; J1.18 56.15,40.12 ; J1.22 58.15,43.19 ; J1.22 58.15,45.2 ; J1.22 56.15,45.2 ; J1.22 56.15,43.19 ; J1.16 58.15,35.57 ; J1.16 58.15,37.58 ; J1.16 56.15,37.58 ; J1.16 56.15,35.57 ; 37.54,55.83 J6.2 ; J6.2 40.18,58.47 ; J6.2 37.54,58.47 ; J1.6 58.15,22.87 ; J1.6 56.15,22.87 ; J1.6 56.15,24.88 ; J1.6 58.15,24.88 ; 35.13,79.39 J3.4 ; J3.4 37.77,82.03 ; J3.4 37.77,79.39 ; JP1.3 28.94,37.71 ; JP1.3 26.94,35.7 ; JP1.3 28.94,35.7 ; JP1.3 26.94,37.71 ; 30.05,79.39 J3.5 ; J3.5 30.05,82.03 ; J3.5 32.69,79.39 ; J6.3 45.26,58.47 ; J6.3 45.26,55.83 ; J6.3 42.62,58.47 ; 16.78,64.15 JP9.3 ; JP9.3 16.78,66.15 ; JP9.3 18.78,66.15 ; JP9.3 18.78,64.15 ; J1.2 58.15,17.79 ; J1.2 58.15,19.8 ; J1.2 56.15,19.8 ; J1.2 56.15,17.79 ; 9.1,39.58 J2.2 ; J2.2 11.73,39.58 ; J2.2 9.1,42.21 ; 56.15,25.41 J1.8 ; J1.8 56.15,27.42 ; J1.8 58.15,27.42 ; J1.8 58.15,25.41 ; 56.15,66.05 J1.40 ; J1.40 58.15,68.06 ; J1.40 58.15,66.05 ; J1.40 56.15,68.06 ; J1.10 58.15,29.96 ; J1.10 56.15,29.96 ; J1.10 58.15,27.95 ; J1.10 56.15,27.95 ; J1.38 58.15,63.51 ; J1.38 56.15,63.51 ; J1.38 58.15,65.52 ; J1.38 56.15,65.52 ; 12.24,69.54 TP1.1 ; TP1.1 14.93,69.54 ; TP1.1 12.24,66.85 ; TP1.1 14.93,66.85 ; J1.26 58.15,48.27 ; J1.26 56.15,50.28 ; J1.26 56.15,48.27 ; J1.26 58.15,50.28 ; J6.4 45.26,50.75 ; J6.4 42.62,50.75 ; J6.4 45.26,53.39 ; J2.5 16.81,42.21 ; J2.5 16.81,39.58 ; J2.5 14.18,39.58 ; J1.28 58.15,52.82 ; J1.28 56.15,50.81 ; J1.28 58.15,50.81 ; J1.28 56.15,52.82 ; 56.15,22.34 J1.4 ; J1.4 58.15,20.33 ; J1.4 58.15,22.34 ; J1.4 56.15,20.33 ; J3.2 32.69,87.11 ; J3.2 30.05,87.11 ; J3.2 30.05,84.47 ; J1.30 58.15,53.35 ; J1.30 56.15,53.35 ; J1.30 56.15,55.36 ; J1.30 58.15,55.36 ; J2.3 11.73,47.29 ; J2.3 9.1,47.29 ; J2.3 9.1,44.66 ; 56.15,35.04 J1.14 ; J1.14 58.15,33.03 ; J1.14 56.15,33.03 ; J1.14 58.15,35.04 ; 56.15,57.9 J1.32 ; J1.32 58.15,57.9 ; J1.32 56.15,55.89 ; J1.32 58.15,55.89
  BOTTOM w0.559: J1.26 58.15,50.28 ; J1.26 58.15,48.27 ; J1.26 56.15,48.27 ; J1.26 56.15,50.28 ; 56.15,60.97 J1.36 ; J1.36 58.15,62.98 ; J1.36 58.15,60.97 ; J1.36 56.15,62.98 ; J5.1 41.83,4.01 ; J5.1 32.59,4.01 ; J5.1 32.59,13.26 ; J5.1 41.83,13.26 ; 12.24,66.85 TP1.1 ; TP1.1 12.24,69.54 ; TP1.1 14.93,69.54 ; TP1.1 14.93,66.85 ; 16.78,64.15 JP9.3 17.78,63.8 ; 9.1,42.21 J2.2 ; J2.2 9.1,39.58 ; J2.2 11.73,39.58 ; 58.15,17.79 J1.2 56.15,17.79 ; J3.3 37.77,84.47 ; J3.3 35.13,87.11 ; J3.3 37.77,87.11 ; J6.4 45.26,50.75 ; J6.4 42.62,50.75 ; J6.4 45.26,53.39 ; JP1.3 28.94,37.71 ; JP1.3 26.94,35.7 ; JP1.3 28.94,35.7 ; JP1.3 26.94,37.71 ; J2.5 16.81,39.58 ; J2.5 14.18,39.58 ; J2.5 16.81,42.21 ; J6.3 45.26,58.47 ; J6.3 45.26,55.83 ; J6.3 42.62,58.47 ; 56.15,25.41 J1.8 ; J1.8 58.15,27.42 ; J1.8 56.15,27.42 ; J1.8 58.15,25.41 ; J2.3 11.73,47.29 ; J2.3 9.1,47.29 ; J2.3 9.1,44.66 ; 56.15,24.88 J1.6 ; J1.6 58.15,22.87 ; J1.6 58.15,24.88 ; J1.6 56.15,22.87 ; 26.56,52.82 JP6.3 28.56,52.82 ; 14.18,47.29 J2.4 ; J2.4 16.81,47.29 ; J2.4 16.81,44.66 ; 56.15,52.82 J1.28 ; J1.28 58.15,52.82 ; J1.28 56.15,50.81 ; J1.28 58.15,50.81 ; 56.15,22.34 J1.4 58.15,22.34 ; 16.27,59.17 JP4.3 ; JP4.3 18.28,57.16 ; JP4.3 16.27,57.16 ; 56.15,63.51 J1.38 ; J1.38 58.15,63.51 ; J1.38 58.15,65.52 ; J1.38 56.15,65.52 ; 55.85,33.48 J1.14 55.8,34.04 ; 56.15,47.74 J1.24 ; J1.24 58.15,45.73 ; J1.24 58.15,47.74 ; J1.24 56.15,45.73 ; 56.15,45.2 J1.22 ; J1.22 58.15,43.19 ; J1.22 56.15,43.19 ; J1.22 58.15,45.2 ; J1.40 58.15,66.05 ; J1.40 56.15,66.05 ; J1.40 56.15,68.06 ; J1.40 58.15,68.06 ; J1.30 58.15,53.35 ; J1.30 56.15,53.35 ; J1.30 58.15,55.36 ; J1.30 56.15,55.36 ; 37.54,55.83 J6.2 ; J6.2 40.18,58.47 ; J6.2 37.54,58.47 ; 35.13,79.39 J3.4 ; J3.4 37.77,79.39 ; J3.4 37.77,82.03 ; 58.15,38.11 J1.18 56.15,38.11 ; 56.15,37.58 J1.16 58.15,37.58 ; 55.85,30.94 57.15,31.5 55.8,31.5 ; 58.15,27.95 J1.10 56.15,27.95 ; 58.15,42.66 J1.20 56.15,42.66 ; J1.32 58.15,55.89 ; J1.32 56.15,57.9 ; J1.32 56.15,55.89 ; J1.32 58.15,57.9 ; J3.5 32.69,79.39 ; J3.5 30.05,79.39 ; J3.5 30.05,82.03 ; J1.34 58.15,60.44 ; J1.34 56.15,60.44 ; J1.34 58.15,58.43 ; J1.34 56.15,58.43 ; 30.05,87.11 J3.2 ; J3.2 30.05,84.47 ; J3.2 32.69,87.11 ; 40.65,52.07 J6.5 38.86,53.86 ; 44.7,29.26 TP3.1 43.36,28.78
  vias: v1(1.78,78.23) v1(1.78,75.69) v1(1.78,71.88) v1(1.78,69.34) v1(1.78,66.17) v1(1.78,63.63) v1(1.78,59.82) v1(1.78,57.28) v1(1.78,54.1) v1(1.78,51.56) v1(1.78,47.75) v1(1.78,45.21) v1(1.78,40.77) v1(1.78,38.23) v1(1.78,34.42) v1(1.78,31.88) v1(1.78,27.43) v1(1.78,24.89) v1(1.78,22.99) v1(1.78,20.45) v1(1.78,16.64) v1(1.78,14.1) v1(1.78,9.65) v1(1.78,7.11) v1(3.05,76.96) v1(3.05,70.61) v1(3.05,64.9) v1(3.05,58.55) v1(3.05,52.83) v1(3.05,46.48) v1(3.05,39.5) v1(3.05,33.15) v1(3.05,26.16) v1(3.05,21.72) v1(3.05,15.37) v1(3.05,8.38) v1(4.32,78.23) v1(4.32,75.69) v1(4.32,71.88) v1(4.32,69.34) v1(4.32,66.17) v1(4.32,63.63) v1(4.32,59.82) v1(4.32,57.28) v1(4.32,54.1) v1(4.32,51.56) v1(4.32,47.75) v1(4.32,45.21) v1(4.32,40.77) v1(4.32,38.23) v1(4.32,34.42) v1(4.32,31.88) v1(4.32,27.43) v1(4.32,24.89) v1(4.32,22.99) v1(4.32,20.45) v1(4.32,16.64) v1(4.32,14.1) v1(4.32,9.65) v1(4.32,7.11) v1(5.59,38.23) v1(5.59,35.69) v1(5.59,23.62) v1(5.59,21.08) v1(6.86,87.12) v1(6.86,84.58) v1(6.86,36.96) v1(6.86,31.88) v1(6.86,29.34) v1(6.86,22.35) v1(8.13,85.85) v1(8.13,38.23) v1(8.13,35.69) v1(8.13,30.61) v1(8.13,23.62) v1(8.13,21.08) v1(9.4,87.12) v1(9.4,84.58) v1(9.4,31.88) v1(9.4,29.34) v1(10.03,64.26) v1(10.03,61.72) v1(10.03,56.01) v1(10.03,53.47) v1(11.3,62.99) v1(11.3,54.74) v1(11.3,37.59) v1(11.3,35.05) v1(11.94,33.15) v1(11.94,30.61) v1(12.57,87.12) v1(12.57,84.58) v1(12.57,64.26) v1(12.57,61.72) v1(12.57,56.01) v1(12.57,53.47) v1(12.57,36.32) v1(13.21,31.88) v1(13.84,85.85) v1(13.84,37.59) v1(13.84,35.05) v1(14.48,33.15) v1(14.48,30.61) v1(15.11,87.12) v1(15.11,84.58) v1(17.4,44.7) v1(17.4,42.16) v1(17.65,35.69) v1(17.65,33.15) v1(18.92,34.42) v1(19.56,87.12) v1(19.56,84.58) v1(19.56,44.96) v1(19.68,42.04) v1(20.19,35.69) v1(20.19,33.15) v1(20.83,85.85) v1(22.1,87.12) v1(22.1,84.58) v1(22.1,41.91) v1(22.1,31.88) v1(22.1,29.34) v1(23.37,30.61) v1(23.62,41.91) v1(24.64,31.88) v1(24.64,29.34) v1(25.27,80.77) v1(25.27,78.23) v1(25.27,4.57) v1(25.27,2.03) v1(25.4,41.91) v1(25.91,87.12) v1(25.91,84.58) v1(26.54,79.5) v1(26.54,3.3) v1(26.8,42.16) v1(27.18,85.85) v1(27.81,80.77) v1(27.81,78.23) v1(27.81,4.57) v1(27.81,2.03) v1(28.45,87.12) v1(28.45,84.58) v1(29.48,44.94) v1(29.48,43.94) v1(29.48,42.94) v1(30.1,67.69) v1(30.35,31.88) v1(30.35,29.34) v1(30.48,44.94) v1(30.48,43.94) v1(30.48,42.94) v1(31.48,44.94) v1(31.48,43.94) v1(31.48,42.94) v1(31.62,30.61) v1(32.39,75.82) v1(32.39,73.02) v1(32.64,78.99) v1(32.64,70.99) v1(32.64,67.69) v1(32.89,31.88) v1(32.89,29.34) v1(35.18,78.99) v1(35.18,70.99) v1(35.31,77.47) v1(35.43,75.82) v1(35.43,74.3) v1(39.24,76.96) v1(39.24,74.42) v1(39.88,87.12) v1(39.88,84.58) v1(40.51,75.69) v1(41.15,85.85) v1(41.78,76.96) v1(41.78,74.42) v1(42.42,87.12) v1(42.42,84.58) v1(42.42,62.99) v1(42.42,60.45) v1(43.05,16) v1(43.05,13.46) v1(43.05,4.57) v1(43.05,2.03) v1(43.69,61.72) v1(44.32,74.42) v1(44.32,71.88) v1(44.32,14.73) v1(44.32,3.3) v1(44.96,62.99) v1(44.96,60.45) v1(45.59,73.15) v1(45.59,16) v1(45.59,13.46) v1(45.59,4.57) v1(45.59,2.03) v1(46.23,47.75) v1(46.23,45.21) v1(46.86,74.42) v1(46.86,71.88) v1(46.86,56.01) v1(46.86,53.47) v1(47.5,46.48) v1(48.13,54.74) v1(48.77,47.75) v1(48.77,45.21) v1(49.4,78.23) v1(49.4,75.69) v1(49.4,63.63) v1(49.4,61.09) v1(49.4,56.01) v1(49.4,53.47) v1(50.04,19.81) v1(50.04,17.27) v1(50.67,76.96) v1(50.67,62.36) v1(50.67,50.93) v1(50.67,48.39) v1(50.67,25.53) v1(50.67,22.99) v1(51.31,18.54) v1(51.94,87.12) v1(51.94,84.58) v1(51.94,78.23) v1(51.94,75.69) v1(51.94,63.63) v1(51.94,61.09) v1(51.94,58.55) v1(51.94,56.01) v1(51.94,49.66) v1(51.94,24.26) v1(52.58,19.81) v1(52.58,17.27) v1(52.58,4.57) v1(52.58,2.03) v1(53.21,85.85) v1(53.21,57.28) v1(53.21,50.93) v1(53.21,48.39) v1(53.21,25.53) v1(53.21,22.99) v1(53.85,3.3) v1(54.48,87.12) v1(54.48,84.58) v1(54.48,58.55) v1(54.48,56.01) v1(55.12,4.57) v1(55.12,2.03) v1(58.29,77.6) v1(58.29,75.06) v1(58.29,72.52) v1(58.29,69.98) v1(58.93,87.12) v1(58.93,84.58) v1(58.93,10.92) v1(58.93,8.38) v1(58.93,4.57) v1(58.93,2.03) v1(59.56,76.33) v1(59.56,71.25) v1(60.2,85.85) v1(60.2,9.65) v1(60.2,3.3) v1(60.83,77.6) v1(60.83,75.06) v1(60.83,72.52) v1(60.83,69.98) v1(61.47,87.12) v1(61.47,84.58) v1(61.47,10.92) v1(61.47,8.38) v1(61.47,4.57) v1(61.47,2.03) v2(27.05,24.26) v2(27.05,23.56) v2(27.05,22.86) v2(27.05,22.16) v2(27.05,21.46) v2(27.75,24.26) v2(27.75,23.56) v2(27.75,22.86) v2(27.75,22.16) v2(27.75,21.46) v2(28.45,24.26) v2(28.45,23.56) v2(28.45,22.86) v2(28.45,22.16) v2(28.45,21.46) v2(29.15,24.26) v2(29.15,23.56) v2(29.15,22.86) v2(29.15,22.16) v2(29.15,21.46) v2(29.85,24.26) v2(29.85,23.56) v2(29.85,22.86) v2(29.85,22.16) v2(29.85,21.46)
VIN: length 4
  TOP w0.184: U1.17 24.77,43.44 R2.2
ADC_CLK: length 3.8
  TOP w0.184: JP2.2 JP3.2
CLK: length 17
  TOP w0.184: U1.11 29.98,47.74 R4.1 29.46,48.26 29.46,48.36 29.41,48.41 29.41,49.12 29.46,49.18 29.46,50.93 30.23,51.69 30.23,55.5 31.37,56.64 JP5.2
CLK_3V: length 37.4
  TOP w0.381: v1(31.69,55.3) U3.6 34.6,55.3 v1(34.8,55.5) C21.1 ; v1(32.26,74.17) R8.1 ; C8.1 20.45,71.5 v1(20.45,72.01)
  TOP w0.559: TP4.1 40.97,28.78 ; TP4.1 38.28,28.78 ; TP4.1 40.97,26.09 ; TP4.1 38.28,26.09
  BOTTOM w0.559: 21.51,66.5 JP9.1 ; JP9.1 24.21,63.8 ; JP9.1 21.51,63.8 ; 38.28,26.09 TP4.1 ; TP4.1 38.28,28.78 ; TP4.1 40.97,26.09 ; TP4.1 40.97,28.78 ; 21.01,56.82 JP4.1 ; JP4.1 23.7,59.51 ; JP4.1 21.01,59.51 ; JP4.1 23.7,56.82 ; 18.82,70.84 JP8.1 18.82,73.43
  vias: v1(29.72,18.92) v1(30.35,19.94) v1(30.61,17.91) v1(30.99,20.96) v1(31.24,18.92) v1(31.88,17.91) v1(32,21.08) v1(32.26,22.73) v1(32.39,18.92) v1(33.91,23.75) v1(33.91,22.61) v1(34.92,22.23) v1(35.43,25.91) v1(36.2,23.24) v1(36.32,27.43) v1(37.34,26.04) v1(37.46,28.45) v1(37.46,24.26) v1(37.46,22.35) v1(38.48,25.15) v1(38.99,24.26) v1(40.13,25.27) v1(40.26,29.59) v1(41.53,28.32) v1(41.66,26.54)
CLK_OUT: length 5.1
  TOP w0.184: R16.2 J6.1
CLKIN: length 12.6
  TOP w0.184: JP3.1 33.01,64.56 32.71,64.26 30.99,64.26 30.1,63.37 30.1,60.2 27.91,58.01 U3.1
CLKOUT: length 1.8
  TOP w0.178: R16.1 35.27,54.65 U3.5
D0: length 5.4
  TOP w0.178: RN1.16 35.18,39.12 32.18,42.11 U1.1
D1: length 4.9
  TOP w0.178: U1.2 32.37,42.94 34.92,40.39 RN1.15
D2: length 4.6
  TOP w0.178: RN1.14 34.42,41.66 32.63,43.44 U1.3
D3: length 4.3
  TOP w0.178: U1.4 33.27,43.94 34.29,42.93 36.03,42.93
D4: length 4
  TOP w0.178: U1.5 33.79,44.44 34.04,44.2 RN1.12
D5: length 4.1
  TOP w0.178: U1.6 34.15,44.94 34.67,45.47 RN1.11
D6: length 4.4
  TOP w0.178: RN1.10 34.92,46.74 33.63,45.44 U1.7
D7: length 5.3
  TOP w0.178: U1.8 33.44,46.14 35.31,48.01 RN1.9
IN: length 1.1
  TOP w0.184: R2.1 C7.2
INPUT: length 8.6
  TOP w0.184: J2.1 R3.1 C7.1
OE: length 14.1
  TOP w0.178: U3.2 v1(29.54,55.95)
  BOTTOM w0.178: JP4.2 19.81,56.26 20.95,55.12 28.7,55.12 v1(29.54,55.95)
OEN: length 5
  TOP w0.178: U1.22 v1(30.48,40.26)
  BOTTOM w0.178: v1(30.48,40.26) JP1.2
OSC: length 6.9
  TOP w0.184: J3.1 R9.2 C9.1
OSC1: length 5.7
  TOP w0.184: JP2.3 R10.1 R8.2 C9.2
N19763021:
  vias: v1(25.78,49.91) v1(26.54,49.91) v1(28.32,49.91) v1(29.34,46.99) v1(30.23,49.78) v1(30.86,46.99) v1(31.24,49.78) v1(32.26,49.53) v1(32.26,47.37) v1(33.15,47.75) v1(34.04,47.75)
N19764908: length 4.2
  TOP w0.178: v1(27.69,47.24) R5.1 ; U1.15 v1(28.33,44.44)
  BOTTOM w0.178: v1(28.33,44.44) 28.57,44.69 28.57,46.35 v1(27.69,47.24)
N19769118: length 2.2
  TOP w0.178: Y1.3 22.58,69.6 R19.2
N19769226: length 3
  TOP w0.178: JP2.1 R19.1
N19785120: length 2.6
  TOP w0.203: U2.14 24.27,22.21 C20.1
N19785142: length 2.2
  TOP w0.203: U2.8 28.45,27.69
N19785144: length 2.9
  TOP w0.203: U2.11 24.35,24.16 R12.2
N19785146: length 2.7
  TOP w0.203: R11.2 23.86,23.51 U2.12
N19785156: length 2.3
  TOP w0.203: 27.05,27.69 27.15,27.59 U2.10
N19799665: length 1.8
  TOP w0.178: R15.2 26.22,55.3 U3.3
N19799687: length 2.5
  TOP w0.184: R18.1 34.04,57.66 33.56,57.18 U3.8
N19799717: length 55.6
  TOP w0.178: v1(36.32,58.55) R18.2
  BOTTOM w0.178: J1.1 59.16,18.8 57.76,20.19 55.04,20.19 54.86,20.37 54.86,26.04 53.21,27.69 47.5,27.69 39.88,35.31 39.88,47.75 36.32,51.31 v1(36.32,58.55)
N19818955: length 28.9
  TOP w0.178: RN1.1 54.48,39.12 55.75,37.85 61.34,37.85 61.85,38.35 61.85,44.58 J1.23
N19818957: length 22.5
  TOP w0.178: RN1.2 43.09,40.26 60.71,40.26 61.09,40.64 61.09,42.8 J1.21
N19818959: length 17.8
  TOP w0.178: J1.19 58.42,42.93 55.5,42.93 54.23,41.66 RN1.3
N19818961: length 18.3
  TOP w0.178: v1(45.59,42.93) 42.96,42.93
  BOTTOM w0.178: v1(45.59,42.93) 48.39,42.93 51.05,40.26 58.55,40.26 J1.17
N19819026: length 35.9
  TOP w0.178: v1(44.83,48.01) RN1.8
  BOTTOM w0.178: J1.9 58.55,30.1 46.23,30.1 42.93,33.4 42.93,46.1 v1(44.83,48.01)
N19819028: length 31.8
  TOP w0.178: v1(44.96,46.74) RN1.7
  BOTTOM w0.178: 59.69,31.5 58.55,32.64 45.97,32.64 43.69,34.92 43.69,45.47 v1(44.96,46.74)
N19819030: length 26.9
  TOP w0.178: RN1.6 v1(44.96,45.47)
  BOTTOM w0.178: v1(44.96,45.47) 44.58,45.09 44.58,37.08 46.48,35.18 58.55,35.18 J1.13
N19819032: length 35
  TOP w0.178: RN1.5 52.83,44.2 53.98,45.34 58.17,45.34 58.42,45.59 58.42,47.5 58.8,47.88 60.71,47.88 62.61,45.97 62.61,37.21 61.98,36.58 J1.15
N19819185: length 6.6
  BOTTOM w0.178: JP5.1 32,64.01 30.73,64.01 28.96,65.79 JP3.3
N19819218: length 9.8
  TOP w0.178: R15.1 25.15,60.83 26.42,62.1 JP5.3
N19819979: length 4.6
  TOP w0.254: R5.2 v1(27.69,49.28) 27.69,49.91 26.29,51.31 25.53,51.31 JP6.2
N19821064: length 2.7
  TOP w0.254: Y1.1 20.36,65.19 JP9.2
N19821339: length 2.8
  TOP w0.254: 17.53,69.6 17.54,69.58 Y1.4

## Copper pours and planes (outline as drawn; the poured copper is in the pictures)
5V on TOP: 5.59,1.78 5.59,16.89 7.75,19.05 13.97,19.05 16.13,16.89 19.81,16.89 23.5,13.21 23.5,1.78
5V on BOTTOM: 5.59,1.78 5.59,16.89 7.75,19.05 10.79,19.05 10.86,18.99 14.03,18.99 15.75,17.27 19.3,17.27 23.5,13.08 23.5,1.78
+3V on TOP: 41.15,18.16 41.15,23.11 43.56,25.53 46.99,25.53 46.99,33.66 31.5,33.66 31.5,33.78 22.73,33.78 22.73,41.02 22.86,41.15 27.18,41.15 27.18,39.62 34.29,39.62 36.96,36.96 36.96,36.58 50.29,36.58 50.29,20.19 48.26,18.16
+3V on TOP: 22.86,44.45 22.86,44.7 20.45,44.7 20.45,54.48 24.13,54.48 24.26,54.36 24.26,52.7 23.88,52.32 23.88,50.55 23.62,50.29 23.24,50.29 22.35,49.4 22.23,49.4 22.23,47.24 22.86,47.24 22.86,48.13 27.05,48.13 27.05,46.99 28.57,46.99 28.57,45.47 29.21,45.47 29.21,44.45
+3V on BOTTOM: 41.15,18.16 41.15,23.11 43.56,25.53 47.37,25.53 48.26,24.64 48.26,18.16
+3V on BOTTOM: 22.86,48.13 27.05,48.13 27.05,46.99 28.57,46.99 28.57,45.47 29.21,45.47 29.21,44.45 27.18,44.45 27.18,38.86 26.8,38.48 22.86,38.48
+5V on TOP: 11.68,24.64 11.68,17.27 27.18,17.27 27.18,20.57 26.04,21.72 26.04,24.64
+5V on BOTTOM: 11.68,24.64 11.68,20.57 13.21,20.57 16,17.78 19.94,17.78 20.45,17.27 27.18,17.27 27.18,20.57 26.04,21.72 26.04,24.64
GND on TOP: 1.27,1.27 1.27,87.63 62.23,87.63 62.23,1.27 ; 6 cut-outs
GND on BOTTOM: 1.27,1.27 1.27,87.63 62.23,87.63 62.23,1.27 ; 2 cut-outs
GND on GND1, GND2: 1.27,1.27 1.27,87.63 62.23,87.63 62.23,1.27
CLK_3V on TOP: 29.34,17.4 29.34,20.57 30.73,20.57 30.73,23.11 32.39,23.11 34.92,25.65 34.92,26.67 38.23,29.97 40.64,29.97 41.91,28.7 41.91,26.29 39.37,23.75 39.37,21.46 32.77,21.46 32.77,17.4
CLK_3V on BOTTOM: 29.34,17.4 29.34,20.57 30.73,20.57 30.73,23.11 32.39,23.11 34.92,25.65 34.92,48.13 32,51.05 32,51.31 29.97,53.34 30.23,53.59 30.23,56.77 25.4,56.77 24.38,55.75 20.7,55.75 18.48,57.98 18.48,64.45 16.51,66.42 16.51,72.39 19.18,75.06 32.51,75.06 32.51,73.66 31.69,72.83 22.29,72.83 21.34,71.88 21.34,67.41 22.48,66.26 22.51,66.26 27.43,61.34 35.05,61.34 36.58,59.82 36.58,55.12 41.91,49.78 41.91,26.29 39.37,23.75 39.37,21.46 32.77,21.46 32.77,17.4 ; 2 cut-outs
N19763021 on TOP: 25.53,50.16 25.53,48.39 27.81,48.39 28.07,48.13 28.07,47.24 28.19,47.12 28.83,47.12 28.83,45.85 30.86,45.85 30.86,46.48 31.37,46.99 34.29,46.99 34.29,50.16
N19763021 on BOTTOM: 25.53,50.16 25.53,48.39 27.81,48.39 28.07,48.13 28.07,47.24 28.19,47.12 28.83,47.12 28.83,45.85 30.86,45.85 30.86,46.48 31.37,46.99 34.29,46.99 34.29,48.01 32.13,50.16

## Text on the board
BOTTOM: BOTTOM SIDE
Board Geometry/Soldermask Bottom: SOLDERMASK BOTTOM
Ref Des/Silkscreen Bottom: SILKSCREEN BOTTOM
User.Comments: ADC08351EVM REV A | SEE NOTE 3 | ASSEMBLY DRAWING,
TOP: TOP SIDE
Ref Des/Assembly Top: GND
Board Geometry/Soldermask Top: SOLDERMASK TOP
Ref Des/Silkscreen Top: SILKSCREEN TOP | GND | 19 | 29 | ADC08351 EVM | REV A
GND1: GROUND PLANE 1
GND2: GROUND PLANE 2
PAGE_OUTLINE: PASTEMASK TOP
PASTEMASK_BOTTOM: PASTEMASK BOTTOM
User.8: ASSEMBLY MUST BE RoHS COMPLIANT AND LEAD FREE. | 1. REFER TO ODB++ FILE FOR SPECIFIC COMPONENT LOCATION INFORMATION. | 2. USE WATER SOLUBLE FLUX DURING BOARD ASSEMBLY. | 3. MARK BOARD'S SILKSCREEN WITH THE SERIAL NUMBER. | 4. IPC-A-610 / ACCEPTABILITY OF ELECTRONIC ASSEMBLIES, CLASS2, CURRENT REVISION. | 5. REMOVE THE METAL TAB ON THE BANANA JACKS BEFORE MOUNTING THEM ONE | THE BOARD. USE LOCTITE THREADLOCKER BLUE 242 (OR EQUIVALENT) WHEN | INSTALLING THE BANANAN JACKS. | THIS DRAWING IS INTENDED TO HELP IN THE ASSEMBLY OF THE DESIGN.
User.11: FIGURE | SIZE | 10.0 | 12.0 | 38.0 | 40.0 | 42.0 | 62.0 | 67.0 | 125.0 | 315.0 | DRILL CHART: TOP to BOTTOM | ALL UNITS ARE IN MILS | PLATED | QTY | 447 | 25 | 2 | 21 | 4 | 40 | 3 | 12
